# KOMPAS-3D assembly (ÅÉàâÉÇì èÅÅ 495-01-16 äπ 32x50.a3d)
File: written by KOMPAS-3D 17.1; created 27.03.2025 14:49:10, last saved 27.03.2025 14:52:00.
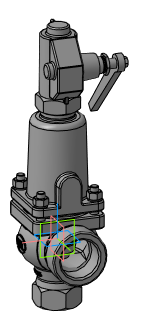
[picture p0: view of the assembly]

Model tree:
1. Операция без истории:1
